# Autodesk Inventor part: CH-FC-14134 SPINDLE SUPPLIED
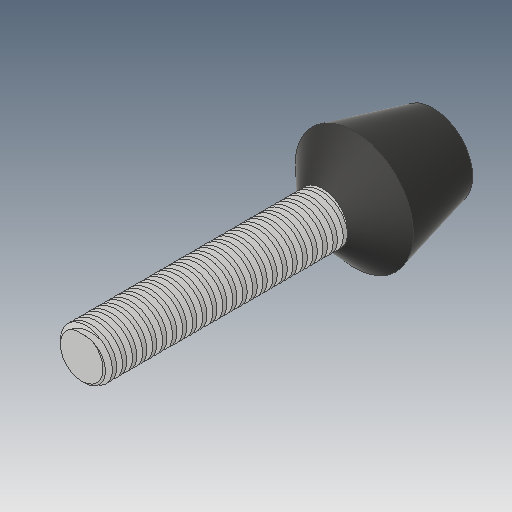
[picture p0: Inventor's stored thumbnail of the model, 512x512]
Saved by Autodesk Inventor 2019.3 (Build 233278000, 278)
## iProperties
Created: 2015-08
Part Number: CH-FC-14134 SPINDLE SUPPLIED
Material: Ogólny
Document SubType Name: Modeling
Designer: CADENGINEERING4
Density: 1 g/cm^3
Appearance: Domyślna
Author: CADENGINEERING4
Revision Number: ÈÎºÎ
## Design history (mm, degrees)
feature "NONE"
node "Bryła1"
